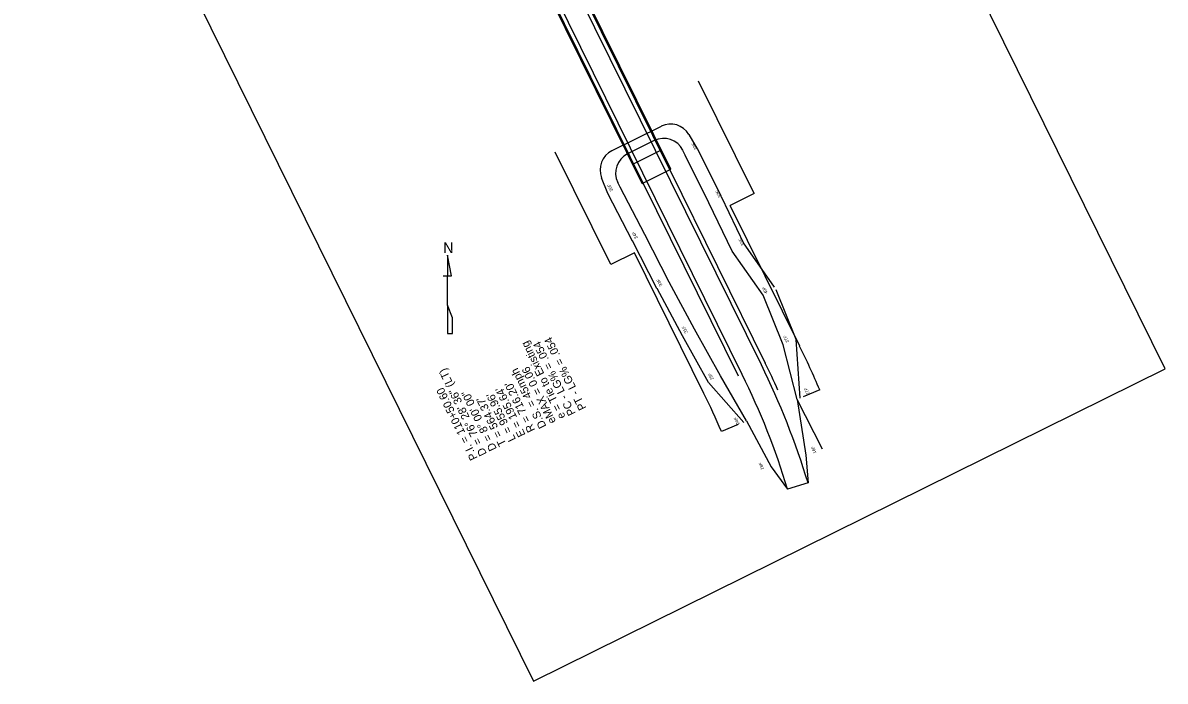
# Model space of a CAD drawing. Extents: x 2186914 to 2187984, y 1080077 to 1082015.
# Drawn here: x 2186914 to 2187984, y 1080755 to 1081371 of the extents above; entities that cross this region are included whole.
import ezdxf

# ---------------------------------------------------------------- set-up
doc = ezdxf.new("R2010")
doc.units = 0
for name, color, linetype in [('RD_EX_Misc', 7, 'Continuous'), ('RD_HC_Data', 7, 'Continuous'), ('RD_PD_Bridge', 7, 'Continuous'), ('RD_PD_CstnLmt', 7, 'Continuous'), ('RD_PD_CstnLmt_TX', 7, 'Continuous'), ('RD_PD_DR_ErosCtrl', 7, 'Continuous'), ('RD_PD_Final_TrvlWay', 7, 'Continuous'), ('RD_PD_GR', 7, 'Continuous'), ('RD_PD_RW', 7, 'Continuous'), ('RD_Sketch2', 7, 'Continuous')]:
    doc.layers.add(name, color=color, linetype=linetype)

# ---------------------------------------------------------------- blocks, each defined once
blk = doc.blocks.new('NA')
at = {"layer": 'RD_EX_Misc'}
for p, q in [((7.9, 31.1), (0.1, 70.3)), ((0.1, 70.3), (0.1, 70.3)), ((0.1, 70.3), (0.1, 31.1)), ((-7.8, 31.1), (0.1, 31.1)), ((0.1, -23.3), (0.1, 31.1)), ((0.1, 31.1), (7.9, 31.1)), ((7.9, 31.1), (7.9, 31.5)), ((9.9, -47.3), (0.1, -23.3)), ((0.1, -23.3), (0.1, -76.7)), ((9.9, -76.7), (9.9, -47.1)), ((9.9, -47.1), (9.9, -47.3)), ((0.1, -76.7), (9.9, -76.7))]:
    blk.add_line(p, q, dxfattribs=at)
blk.add_text('N', height=20, dxfattribs=at).set_placement((-7.8, 74))

msp = doc.modelspace()

# ---------------------------------------------------------------- linework, layer by layer
at = {"layer": 'RD_PD_Bridge'}
for p, q in [((2187520.2, 1081233.3), (2187422.7, 1081430.5)), ((2187521.1, 1081233.7), (2187423.6, 1081431)), ((2187521.2, 1081233.8), (2187423.7, 1081431)), ((2187494.3, 1081220.5), (2187396.8, 1081417.7)), ((2187494.4, 1081220.5), (2187396.9, 1081417.7)), ((2187495.2, 1081220.9), (2187397.8, 1081418.2)), ((2187512.3, 1081251.7), (2187485.4, 1081238.4))]:
    msp.add_line(p, q, dxfattribs=at)
msp.add_lwpolyline([(2187521.2, 1081233.8), (2187512.3, 1081251.7), (2187485.4, 1081238.4), (2187494.3, 1081220.5)], close=True, dxfattribs=at)
at = {"layer": 'RD_PD_CstnLmt'}
for p, q in [((2187505.7, 1081260.6), (2187480.6, 1081248.2)), ((2187534.7, 1081247.1), (2187532.5, 1081251.5)), ((2187557, 1081202.4), (2187534.7, 1081247.1)), ((2187473.7, 1081217), (2187471.6, 1081221.4)), ((2187496.8, 1081172.6), (2187473.7, 1081217)), ((2187578.7, 1081157.3), (2187557, 1081202.4)), ((2187519.8, 1081128.2), (2187496.8, 1081172.6)), ((2187607.7, 1081115.9), (2187578.7, 1081157.3)), ((2187543.5, 1081084.2), (2187519.8, 1081128.2)), ((2187626.6, 1081069.4), (2187607.7, 1081115.9)), ((2187567.9, 1081040.4), (2187543.5, 1081084.2)), ((2187639.5, 1081018.3), (2187626.6, 1081069.4)), ((2187592.2, 1080998.3), (2187567.9, 1081040.4)), ((2187663.3, 1080971.7), (2187639.5, 1081018.3)), ((2187639.5, 1081018.3), (2187647.7, 1080966.3)), ((2187592.2, 1080998.3), (2187615.4, 1080955.3)), ((2187647.7, 1080966.3), (2187649.8, 1080940.3)), ((2187615.4, 1080955.3), (2187630.7, 1080934.4))]:
    msp.add_line(p, q, dxfattribs=at)
for centre, start, end in [((2187514.6, 1081242.7), 26.2966, 116.2966), ((2187489.5, 1081230.3), 116.2966, 206.2966)]:
    msp.add_arc(centre, 20, start, end, dxfattribs=at)
at = {"layer": 'RD_PD_DR_ErosCtrl'}
for p, q in [((2187512.3, 1081274), (2187466, 1081251.1)), ((2187546.3, 1081252.9), (2187538.3, 1081266.3)), ((2187568.7, 1081208.2), (2187546.3, 1081252.9)), ((2187462.2, 1081211), (2187456.3, 1081225.8)), ((2187485.3, 1081166.6), (2187462.2, 1081211)), ((2187590.4, 1081163), (2187568.8, 1081208)), ((2187508.2, 1081122.3), (2187485.3, 1081166.7)), ((2187618.4, 1081123.4), (2187589.4, 1081164.8)), ((2187532.1, 1081078), (2187508.3, 1081122.1)), ((2187638.6, 1081074.3), (2187619.8, 1081120.8)), ((2187556.5, 1081034.1), (2187532.2, 1081077.9)), ((2187642.3, 1081019.4), (2187638.6, 1081074.3)), ((2187589.6, 1080996.8), (2187556.5, 1081034.1))]:
    msp.add_line(p, q, dxfattribs=at)
for centre, start, end in [((2187521.1, 1081256.1), 30.8727, 116.2966), ((2187474.9, 1081233.2), 116.2966, 201.7341)]:
    msp.add_arc(centre, 20, start, end, dxfattribs=at)
at = {"layer": 'RD_PD_Final_TrvlWay'}
for p, q in [((2187606.1, 1081050.6), (2187248.2, 1081774.8)), ((2187588.2, 1081041.8), (2187230.3, 1081766)), ((2187649.8, 1080940.3), (2187630.7, 1080934.4))]:
    msp.add_line(p, q, dxfattribs=at)
for radius in [726.2, 706.2]:
    msp.add_arc((2186955, 1080728.9), radius, 16.9205, 26.2966, dxfattribs=at)
at = {"layer": 'RD_PD_GR'}
for p, q in [((2187520.3, 1081233.3), (2187609.7, 1081052.4)), ((2187584.6, 1081040), (2187495.2, 1081220.9))]:
    msp.add_line(p, q, dxfattribs=at)
msp.add_arc((2186955, 1080728.9), 730.2, 24.0983, 26.2966, dxfattribs=at)
at = {"layer": 'RD_PD_RW'}
for p, q in [((2187599.3, 1081211), (2187547.3, 1081316.4)), ((2187464.9, 1081144.6), (2187412.8, 1081249.9)), ((2187599.3, 1081211), (2187576.9, 1081200)), ((2187642, 1081068.3), (2187576.9, 1081200)), ((2187487.3, 1081155.7), (2187464.9, 1081144.6)), ((2187552.3, 1081024), (2187487.3, 1081155.7)), ((2187660.7, 1081027.3), (2187645.1, 1081020.7)), ((2187584.3, 1080995), (2187568.6, 1080988.4))]:
    msp.add_line(p, q, dxfattribs=at)
for radius in [766.2, 666.2]:
    msp.add_arc((2186955, 1080728.9), radius, 22.9213, 26.2966, dxfattribs=at)
at = {"layer": 'RD_Sketch2'}
msp.add_lwpolyline([(2187984.4, 1081047), (2187505.9, 1082015.2), (2186914.2, 1081722.9), (2187392.7, 1080754.6)], close=True, dxfattribs=at)

# ---------------------------------------------------------------- block references
at = {"layer": 'RD_PD_GR', "xscale": 0.5, "yscale": 0.5}
msp.add_blockref('NA', (2187311.9, 1081118.4), dxfattribs=at)

# ---------------------------------------------------------------- texts
at = {"layer": 'RD_HC_Data'}
for s, rotation, p in [('e = Tie to Existing', 116.3746, (2187422.8, 1081002.2)), ('PT - LG% = .054', 116.3712, (2187442.3, 1081010.4)), ('PC - LG% = .054', 116.3712, (2187432.3, 1081005.4)), ('    = 76%%d 28\' 36" (LT)', 115.9066, (2187349.4, 1080967.8)), ('D.S. = 45mph', 116.3746, (2187404.9, 1080993.3)), ('eMAX = 0.06', 116.3746, (2187413.9, 1080997.8)), ("R = 716.20'", 115.9066, (2187394.3, 1080989.7)), ('P.I. = 110+50.60', 115.9066, (2187340.4, 1080963.5)), ('D = 8%%d 00\' 00"', 115.9066, (2187358.4, 1080972.2)), ("L = 955.96'", 115.9066, (2187376.3, 1080981)), ("E = 195.64'", 115.9066, (2187385.3, 1080985.3)), ("T = 564.37'", 115.9066, (2187367.3, 1080976.6)), ('D', 116.7887, (2187349.1, 1080967.6))]:
    msp.add_text(s, height=7.5, rotation=rotation, dxfattribs=at).set_placement(p)
at = {"layer": 'RD_PD_CstnLmt_TX'}
for s, rotation, p in [('33F', 116.2966, (2187546.3, 1081252.9)), ('35F', 116.2966, (2187467.4, 1081213.9)), ('33F', 116.2966, (2187568.7, 1081208.2)), ('34F', 116.2966, (2187490.5, 1081169.5)), ('33F', 116.2966, (2187590.4, 1081163.1)), ('33F', 116.2966, (2187513.5, 1081125.1)), ('40F', 116.2966, (2187612.2, 1081118.1)), ('31F', 116.2966, (2187537.2, 1081081.1)), ('37F', 116.2966, (2187632.3, 1081072.3)), ('29F', 116.2966, (2187561.6, 1081037.3)), ('27F', 112.9213, (2187651.5, 1081023.4)), ('24F', 112.9213, (2187585.7, 1080995.6)), ('16F', 108.9213, (2187657.6, 1080968.2)), ('18F', 108.9213, (2187608.7, 1080953))]:
    msp.add_text(s, height=3, rotation=rotation, dxfattribs=at).set_placement(p)

doc.saveas('drawing.dxf')
